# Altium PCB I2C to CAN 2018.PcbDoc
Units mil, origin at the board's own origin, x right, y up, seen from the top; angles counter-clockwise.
Board outline 2285 x 2910 mil, 2 copper layers (Top Layer, Bottom Layer), stack 62 mil thick; 55 components, 23 nets, 109 pads, 24 vias.
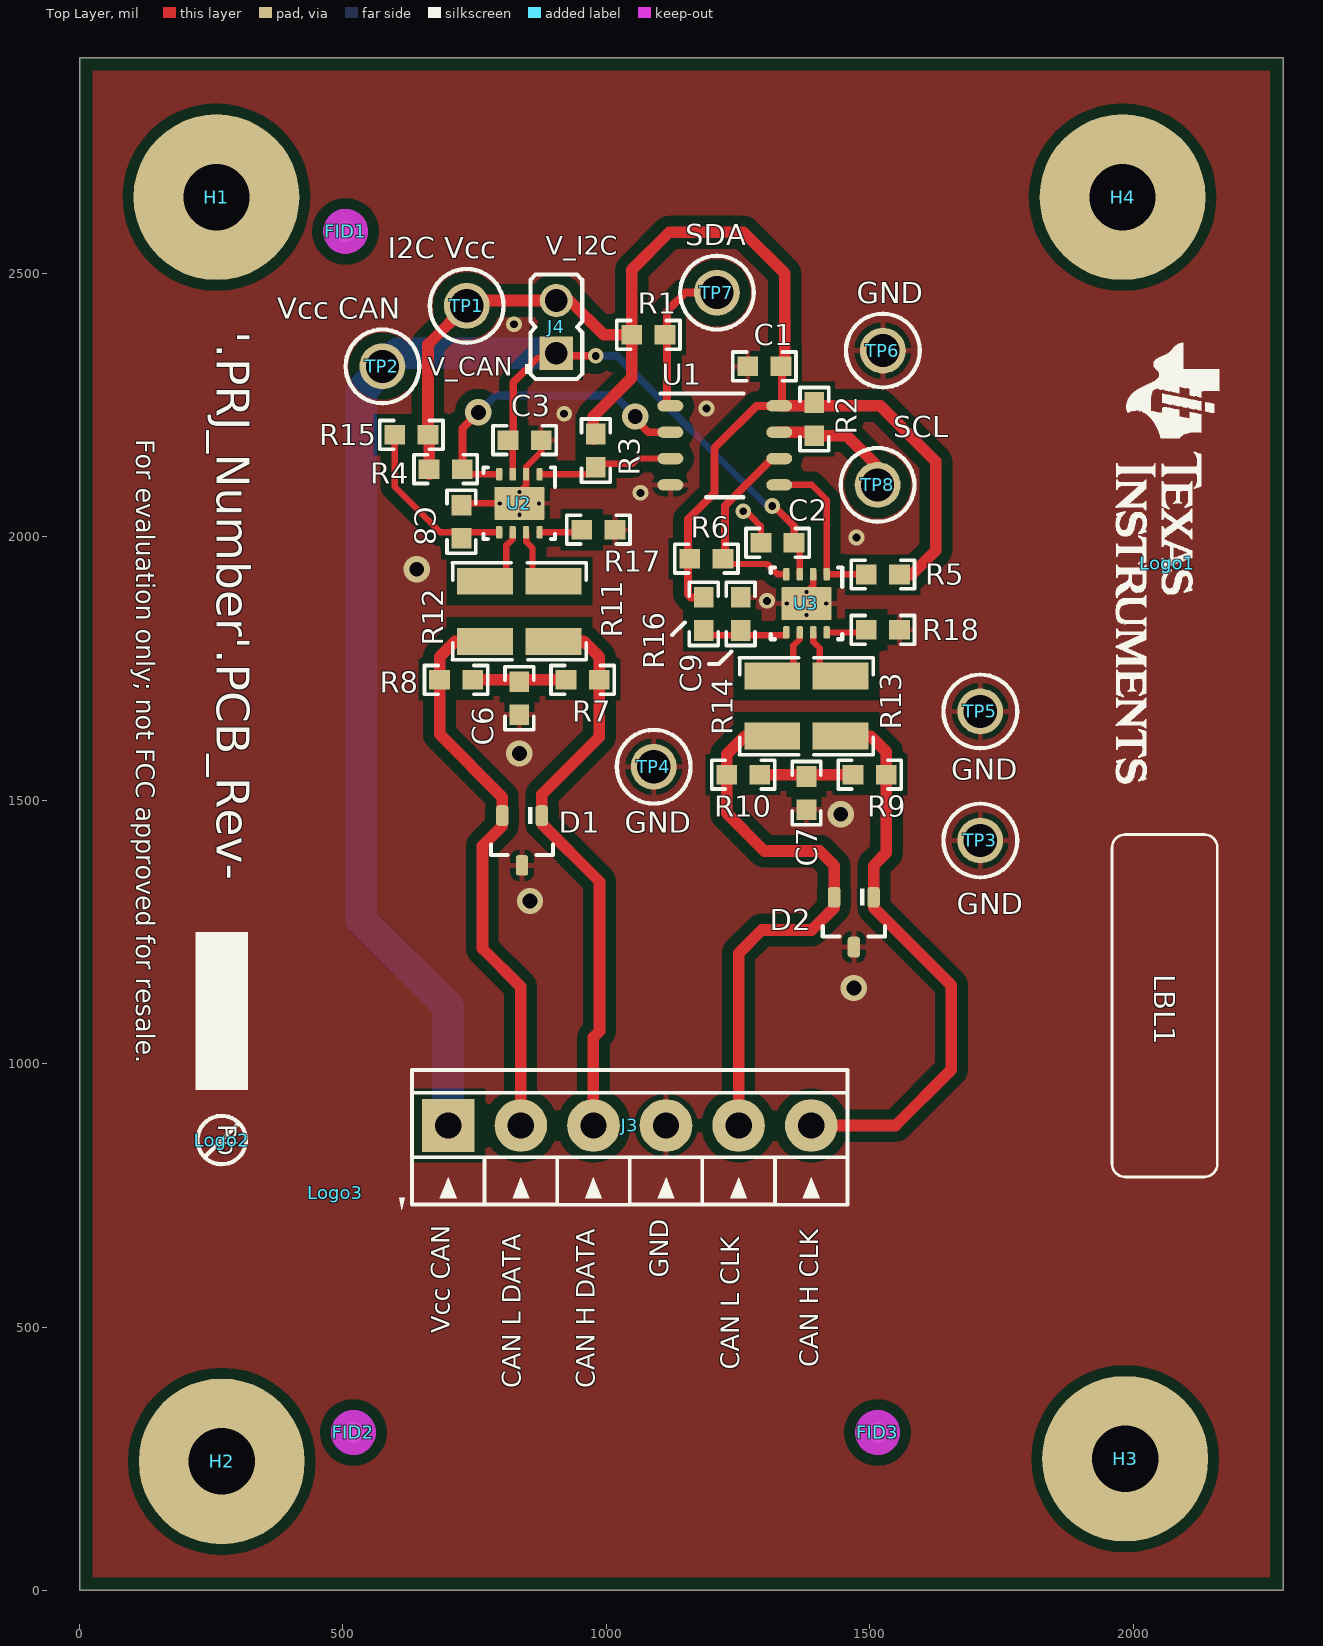
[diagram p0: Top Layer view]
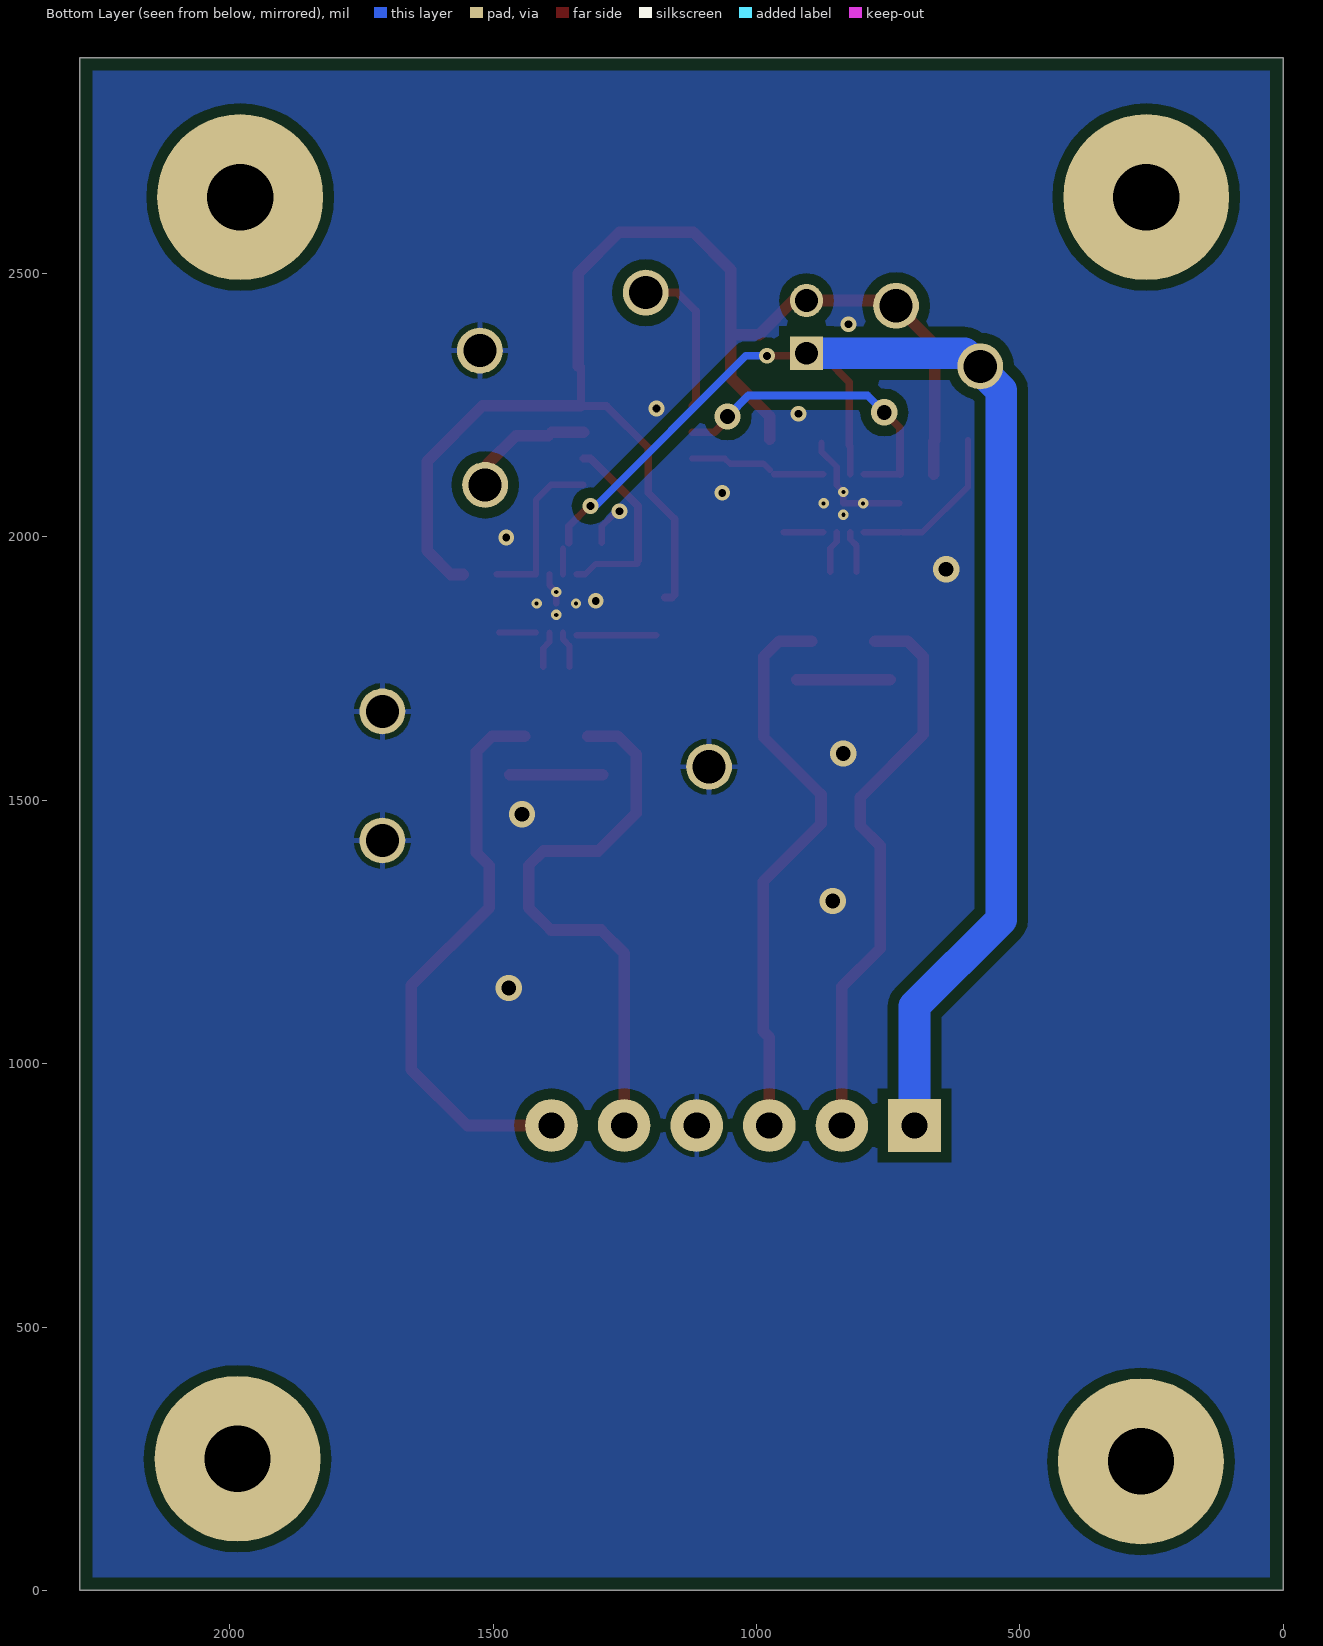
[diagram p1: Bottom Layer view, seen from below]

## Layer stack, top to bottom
Top Solder: solder mask 0.4, Solder Resist, Dk 3.5
Top Layer: signal copper 1.4
Dielectric1: core 59.2, FR-4, Dk 4.8
Bottom Layer: signal copper 1.4
Bottom Solder: solder mask 0.4, Solder Resist, Dk 3.5

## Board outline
0,0 2285,0 2285,2910 0,2910

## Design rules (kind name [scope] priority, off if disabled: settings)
AcuteAngle [All] p1: minimum=4.50000000000000E+0001 checktracksonly=FALSE
AssemblyTestPointUsage [All] p1: valid=2
BoardOutlineClearance BoardOutlineClearance_MountingHoles [OnCopper and InComponentClass('Mounting Holes')] p1: gap=40 ignorepadtopadclearanceinfootprint=FALSE
BoardOutlineClearance BoardOutlineClearance_Poly [OnCopper and IsPoly] p2: gap=25 ignorepadtopadclearanceinfootprint=FALSE
BoardOutlineClearance [OnCopper and Not InComponentClass('Logo') and not InComponentClass('FiducialMark') and not InRegion(1000,500,4000,800) and not InPoly] p3: gap=75 ignorepadtopadclearanceinfootprint=FALSE
Clearance Clearance_Keepouts [((IsTrack Or IsArc) And Not InPoly) And IsFree and IsKeepOut vs ((IsTrack Or IsArc) And Not InPoly) And IsFree and IsKeepOut] p1: gap=0 ignorepadtopadclearanceinfootprint=FALSE
Clearance Clearance_Poly [InPolygon] p2: gap=20 ignorepadtopadclearanceinfootprint=FALSE
Clearance Clearance_FiducialMark [IsKeepOut and InComponentClass('FiducialMark') vs IsPad and InComponentClass('FiducialMark')] p3: gap=0 ignorepadtopadclearanceinfootprint=FALSE
Clearance [All] p4: gap=7.87 ignorepadtopadclearanceinfootprint=FALSE except(0: Arc-Hole Track-Hole SMDPad-Hole THPad-Hole Via-Hole Fill-Hole Poly-Hole Region-Hole Text-Hole)
ComponentClearance ComponentClearance_MountingHoles_FiducialMarks [InComponentClass('Mounting Holes') vs InComponentClass('FiducialMark')] p1: gap=50 collisioncheckmode=3 verticalgap=10 showdistances=FALSE
ComponentClearance ComponentClearance_Shunt [InComponentClass('Header') vs InComponentClass('Shunt')] p2: gap=0 collisioncheckmode=3 verticalgap=0 showdistances=FALSE
ComponentClearance ComponentClearance_Logo [InComponentClass('Logo')] p3: gap=50 collisioncheckmode=3 verticalgap=10 showdistances=FALSE
ComponentClearance ComponentClearance_ScrewToNut [(HasFootprint('NY PMS 440 0025 PH')) vs (HasFootprint('Keystone_1902C'))] p4: gap=5 collisioncheckmode=3 verticalgap=10 showdistances=FALSE
ComponentClearance ComponentClearance_MountingHoles [InComponentClass('Mounting Holes')] p5: gap=250 collisioncheckmode=3 verticalgap=100000 showdistances=FALSE
ComponentClearance ComponentClearance_SmallPassives [HasFootprint('0201*') or HasFootprint('0402*') or HasFootprint('0508') or HasFootprint('0603*') or HasFootprint('0612') or HasFootprint('0805*') or HasFootprint('0815*') or HasFootprint('0830*') or HasFootprint('1206*') or HasFootprint('1210*') or HasFootprint('1808*') or HasFootprint('1812*') or HasFootprint('1825*') or HasFootprint('2010*') or HasFootprint('2220*') or HasFootprint('2225*') or HasFootprint('2512*') or HasFootprint('2728*') or HasFootprint('3518*') vs HasFootprint('0201*') or HasFootprint('0402*') or HasFootprint('0508') or HasFootprint('0603*') or HasFootprint('0612') or HasFootprint('0805*') or HasFootprint('0815*') or HasFootprint('0830*') or HasFootprint('1206*') or HasFootprint('1210*') or HasFootprint('1808*') or HasFootprint('1812*') or HasFootprint('1825*') or HasFootprint('2010*') or HasFootprint('2220*') or HasFootprint('2225*') or HasFootprint('2512*') or HasFootprint('2728*') or HasFootprint('3518*')] p6: gap=14.96 collisioncheckmode=3 verticalgap=10 showdistances=FALSE
ComponentClearance ComponentClearance_THtoSMT [IsThruComponent vs IsSMTComponent] p7: gap=40 collisioncheckmode=3 verticalgap=30 showdistances=FALSE
ComponentClearance ComponentClearance_THtoTH [IsThruComponent vs IsThruComponent] p8: gap=30 collisioncheckmode=3 verticalgap=30 showdistances=FALSE
ComponentClearance [All] p9: gap=30 collisioncheckmode=3 verticalgap=10 showdistances=FALSE
DiffPairsRouting [All] p1: maxlimit=100 minlimit=10 mostfreqgap=10 toplayer_minwidth=15 toplayer_maxwidth=15 toplayer_prefwidth=15 bottomlayer_minwidth=15 bottomlayer_maxwidth=15 bottomlayer_prefwidth=15 maxuncoupledlength=1000
FabricationTestPointUsage TestPointUsage [All] p1: valid=2 allowmultiple=FALSE
FabricationTestpoint Testpoint [All] p1: side=3 testpointundercomponent=TRUE minsize=40 maxsize=100 preferedsize=60 minholesize=0 maxholesize=40 preferedholesize=32 testpointgrid=1 allowsidetop=TRUE allowsidebottom=TRUE usegrid=TRUE gridtolerance=0.01
FanoutControl Fanout_LCC [IsLCC] p1: bgadir=Out bgaviamode=Centered fanoutstyle=Auto fanoutdirection=Alternating viagrid=1 // Fanout_LCC (Default Rule)
FanoutControl Fanout_BGA [IsBGA] p2: bgadir=Out bgaviamode=Centered fanoutstyle=Auto fanoutdirection=Alternating viagrid=1 // Fanout_BGA (Default Rule)
FanoutControl Fanout_Default [All] p4: bgadir=Out bgaviamode=Centered fanoutstyle=Auto fanoutdirection=Alternating viagrid=1 // Fanout_Default (Default Rule)
FanoutControl Fanout_Small [(CompPinCount < 5)] p5: bgadir=Out bgaviamode=Centered fanoutstyle=Auto fanoutdirection=OutThenIn viagrid=1 // Fanout_Small (Default Rule)
HoleSize [All] p1: absolutevalues=TRUE maxlimit=251 minlimit=7.87 maxpercent=80.000 minpercent=20.000
MatchedLengths "Can Length 2" [InNetClass('Can Length 2')] p1: tolerance=5 checknetsindiffpair=FALSE checkdiffpairvsdiffpair=TRUE checkxsignals=TRUE checkothers=TRUE
MinimumAnnularRing MinimumAnnularRing_ThermalPadVias [IsVia and InAnyComponent] p1: minimumring=5.91
MinimumAnnularRing [All] p2: minimumring=7.49
MinimumSolderMaskSliver MinimumSolderMaskSliver_Logo [InComponentClass('Logo') vs InComponentClass('Logo')] p1: minsoldermaskwidth=0.7
MinimumSolderMaskSliver [All] p2: minsoldermaskwidth=3.94
PlaneConnect [All] p1: planeconnectstyle=Relief reliefexpansion=10 reliefentries=4 reliefconductorwidth=10 reliefairgap=10
PolygonConnect "GND Vias Relief" [IsVia AND InNet('GND')] p1: thpad.connectstyle=Relief thpad.reliefconductorwidth=10 thpad.reliefentries=4 thpad.polygonreliefangle="90 Angle" thpad.airgapwidth=10 smdpad.connectstyle=Relief smdpad.reliefconductorwidth=10 smdpad.reliefentries=4 smdpad.polygonreliefangle="90 Angle" smdpad.airgapwidth=10 via.connectstyle=Direct via.reliefconductorwidth=10 via.reliefentries=4 via.polygonreliefangle="90 Angle" via.airgapwidth=10
PolygonConnect [All] p2: connectstyle=Relief reliefconductorwidth=10 reliefentries=4 polygonreliefangle="90 Angle" airgapwidth=10
RoutingVias ThermalPadVias [IsVia and InAnyComponent] p1: holewidth=7.87 width=19.68 viastyle="Through Hole" minholewidth=7.87 minwidth=19.68 maxholewidth=12.99 maxwidth=23.62
RoutingVias [All] p2: holewidth=16 width=34 viastyle="Through Hole" minholewidth=7.87 minwidth=26 maxholewidth=40 maxwidth=65
SilkToBoardRegionClearance [Not ((IsComment or IsDesignator) And (Hide <> 'False')) and not InRegion(1000,500,4000,800)] p1:
SilkToSilkClearance SilkToSilkClearance_Pb-FreeLogo [(HasFootprint('Pb-Free_Overlay_Medium') OR HasFootprint('Pb-Free_Overlay_Small')) vs (HasFootprint('Pb-Free_Overlay_Medium') OR HasFootprint('Pb-Free_Overlay_Small'))] p1: silktosilkclearance=0
SilkToSilkClearance [All] p2: silktosilkclearance=4
SilkToSolderMaskClearance SilkToComponentPadClearance [(IsPad or IsFill or IsRegion) and InAnycomponent] p1: minsilkscreentomaskgap=5 clearancetoexposedcopper=TRUE
SilkToSolderMaskClearance "Silk to Solder Mask Opening" [All] p2: minsilkscreentomaskgap=4 clearancetoexposedcopper=FALSE
SolderMaskExpansion [All] p1: expansion=1.97
Width [All] p1: maxlimit=100 minlimit=6 preferedwidth=10 checkconnectedcopper=TRUE
15 further rules are at their usual default settings.

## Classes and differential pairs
component class "Mounting Holes": H1 H2 H3 H4
net class "Can Length 1": NetR11_2 NetR12_2 NetR13_2 NetR14_2
net class "Can Length 2": "CAN H Clock" "CAN H Data" "CAN L Clock" "CAN L Data"
component class Header: J4
component class "I2C to CAN 2018": C1 C2 C3 C6 C7 C8 C9 D1 D2 J3 J4 R1 R2 R3 R4 R5 R6 R7 R8 R9 R10 R11 R12 R13 R14 R15 R16 R17 R18 TP1 TP2 TP3 TP4 TP5 TP6 TP7 TP8 U1 U2 U3
component class Label: LBL1
component class AssemblyNote: ZZ1 ZZ2 ZZ3 ZZ4
component class FiducialMark: FID1 FID2 FID3
component class EVM_Hardware: FID1 FID2 FID3 H1 H2 H3 H4 LBL1 Logo1 Logo2 Logo3 ZZ1 ZZ2 ZZ3 ZZ4
component class Logo: Logo1

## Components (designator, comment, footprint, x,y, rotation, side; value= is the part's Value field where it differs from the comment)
C1 "885012206020" 0603 1300,2323.7 r180 top value=0.1uF
C2 "885012206020" 0603 1325,1988.7 r180 top value=0.1uF
C3 "885012206020" 0603 845,2183.7 r0 top value=0.1uF
C6 "C1608X5R1H104K080AA" 0603 835,1693.7 r90 top value=0.1uF
C7 "C1608X5R1H104K080AA" 0603 1380,1513.7 r90 top value=0.1uF
C8 "885012206020" 0603 725,2028.7 r90 top value=0.1uF
C9 "885012206020" 0603 1255,1853.7 r90 top value=0.1uF
D1 "NUP2105LT1G" SOT-23 840,1423.7 r270 top value=24V
D2 "NUP2105LT1G" SOT-23 1470,1268.7 r270 top value=24V
FID1 "Fiducial" Fiducial10-20 505,2580 r0 top
FID2 "Fiducial" Fiducial10-20 520,300 r0 top
FID3 "Fiducial" Fiducial10-20 1515,300 r0 top
H1 "NY PMS 440 0025 PH" "NY PMS 440 0025 PH" 260,2645 r90 top
H2 "NY PMS 440 0025 PH" "NY PMS 440 0025 PH" 270,245 r90 top
H3 "NY PMS 440 0025 PH" "NY PMS 440 0025 PH" 1985,250 r90 top
H4 "NY PMS 440 0025 PH" "NY PMS 440 0025 PH" 1980,2645 r90 top
J3 "ED555/6DS" TERM_BLK_ED555-6DS 700,882.7 r0 top
J4 "Vcc Connect" 3M_961102-6404-AR 905,2398.7 r90 top
LBL1 "Size: 0.65\" x 0.20 \"" Label_650x200 2060,1110 r270 top
Logo1 "Texas Instruments" TI_Stacked_Overlay_Small 2065,1950 r270 top
Logo2 "Pb-Free Symbol" Pb-Free_Overlay_Small 270,855 r270 top
Logo3 "FCC disclaimer" FCC_disclaimer 485,755 r270 top
R1 "RT0603BRD074K7L" 0603 1080,2383.7 r180 top value=4.70k
R2 "RT0603BRD074K7L" 0603 1395,2223.7 r90 top value=4.70k
R3 "RT0603BRD074K7L" 0603 980,2163.7 r90 top value=4.70k
R4 "RT0603BRD074K7L" 0603 695,2128.7 r180 top value=4.70k
R5 "RT0603BRD074K7L" 0603 1525,1928.7 r0 top value=4.70k
R6 "RT0603BRD074K7L" 0603 1190,1958.7 r180 top value=4.70k
R7 "CRCW060362R0JNEA" 0603 955,1728.7 r0 top value=62
R8 "CRCW060362R0JNEA" 0603 715,1728.7 r0 top value=62
R9 "CRCW060362R0JNEA" 0603 1500,1548.7 r0 top value=62
R10 "CRCW060362R0JNEA" 0603 1260,1548.7 r0 top value=62
R11 "CRCW12100000Z0EA" 1210 900,1858.7 r90 top value=0
R12 "CRCW12100000Z0EA" 1210 770,1858.7 r90 top value=0
R13 "CRCW12100000Z0EA" 1210 1445,1678.7 r90 top value=0
R14 "CRCW12100000Z0EA" 1210 1315,1678.7 r90 top value=0
R15 "RT0603BRD074K7L" 0603 630,2193.7 r0 top value=4.70k
R16 "RT0603BRD074K7L" 0603 1185,1853.7 r90 top value=4.70k
R17 "RT0603BRD074K7L" 0603 985,2013.7 r180 top value=4.70k
R18 "RT0603BRD074K7L" 0603 1525,1823.7 r180 top value=4.70k
TP1 "I2C Vcc" Keystone5010 735,2438.7 r0 top
TP2 "Vcc CAN" Keystone5010 575,2323.7 r0 top
TP3 "GND" Keystone5011 1710,1423.7 r0 top
TP4 "GND" Keystone5011 1090,1563.7 r0 top
TP5 "GND" Keystone5011 1710,1668.7 r0 top
TP6 "GND" Keystone5011 1525,2353.7 r0 top
TP7 "SDA" Keystone5010 1210,2463.7 r0 top
TP8 "SCL" Keystone5010 1515,2098.7 r0 top
U1 "P82B96D" D0008A_L 1225,2173.7 r0 top
U2 "TCAN1042HGVDRBQ1" DRB0008F 834.99,2063.71 r270 top
U3 "TCAN1042HGVDRBQ1" DRB0008F 1380,1873.7 r270 top
ZZ1 "This Assembly Note is for PCB labels only" AssemblyNoteLabel 185,3938 r0 top
ZZ2 "This Assembly Note will show in the PcbDoc and associated outputs" AssemblyNote 185,3829.11 r0 top
ZZ3 "This Assembly Note will show in the PcbDoc and associated outputs" AssemblyNote 185,3740.56 r0 top
ZZ4 "This Assembly Note will show in the PcbDoc and associated outputs" AssemblyNote 185,3652 r0 top

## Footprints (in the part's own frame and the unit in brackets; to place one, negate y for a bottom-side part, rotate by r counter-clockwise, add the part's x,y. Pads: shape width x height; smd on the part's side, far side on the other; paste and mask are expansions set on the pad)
3M_961102-6404-AR [mm] "Header, 2.54mm, 2x1, TH"
  rect 1.6x1.6 hole 1.1: 1(-1.27,0)
  round 1.6 hole 1.1: 2(1.27,0)
  silkscreen extent -2.52,-1.25 2.52,1.5, body extent -2.52,-1.25 2.52,1.25, height 8.5
0603 [mm] "0603 from SM-752 data"
  rect 1x0.95 smd: 1(-0.8,0) 2(0.8,0)
  silkscreen extent -1.52,-0.69 1.52,0.69, body extent -0.87,-0.47 0.87,0.47, height 1
1210 [mm] "1210 from SM-752 data"
  rect 1.3x2.7 smd: 1(-1.45,0) 2(1.45,0)
  silkscreen extent -2.34,-1.57 2.34,1.27, body extent -1.7,-1.35 1.7,1.35, height 1.35
AssemblyNote [mil] "Assembly Note"
AssemblyNoteLabel [mil] "Assembly Note for PCB Labels"
D0008A_L [mm] "SOIC, 8-Leads, Body 4.9x3.9mm, Pitch 1.27mm, IPC High Density"
  oval 1.25x0.55 smd: 1(-2.625,1.905) 2(-2.625,0.635) 3(-2.625,-0.635) 4(-2.625,-1.905) 5(2.625,-1.905) 6(2.625,-0.635) 7(2.625,0.635) 8(2.625,1.905)
  silkscreen extent -3.1,-2.5 0.9,2.5, body extent -3,-2.45 3,2.45, height 1.63
DRB0008F [mm] "SON, 8-Leads, Body 3x3mm, Pitch 0.65mm, Thermal Pad 2.4x1.6mm, TI Recommended"
  rrect33% 0.6x0.3 smd: 1(-1.4,0.975) 2(-1.4,0.325) 3(-1.4,-0.325) 4(-1.4,-0.975) 5(1.4,-0.975) 6(1.4,-0.325) 7(1.4,0.325) 8(1.4,0.975)
  rrect9% 1.47x1.07 on Top Paste: 9(0,0.635) 9(0,-0.635)
  rrect6% 1.6x2.4 smd paste-1.2: 9(0,0)
  silkscreen extent -1.73,-1.73 1.73,1.73, body extent -1.5,-1.5 1.5,1.5, height 0.77
FCC_disclaimer [mil]
Fiducial10-20 [mm]
  round 1 smd mask+0.5: 1(0,0)
  Top Layer keep-out circle w1.178: c0,0 r0.5
Keystone5010 [mil] "Keystone Multipurpose loops"
  round 87 hole 63: 1(0,0)
  silkscreen extent -70,-70 70,70, body extent -63,-63 63,62, height 319
Keystone5011 [mil] "Keystone Multipurpose loops"
  round 87 hole 63: 1(0,0)
  silkscreen extent -70,-70 70,70, body extent -63,-63 63,62, height 319
Label_650x200 [mil] "Thermal Transfer Label"
  silkscreen extent -325,-100 325,100, body extent -325,-100 325,100, height 1
"NY PMS 440 0025 PH" [mm] "4-40 nylon screw and mounting hole"
  round 8 hole 3.2: 1(0,0)
  body extent -3.3,-3.3 3.3,3.3, height 2.69
Pb-Free_Overlay_Small [mil]
  silkscreen extent -46,-46 46,46
SOT-23 [mm] "SOT23, 3-Leads, Body 2.9x1.3mm, Pitch 0.95mm, Lead Span 2.5mm, IPC Medium Density"
  rrect50% 1x0.6 smd: 1(-1.2,0.95) 2(-1.2,-0.95) 3(1.2,0)
  silkscreen extent -1.63,-1.5 0.7,1.5, body extent -1.16,-1.45 1.21,1.45, height 1
TERM_BLK_ED555-6DS [mm]
  rect 2.54x2.54 hole 1.27: 1(0,0)
  round 2.54 hole 1.27: 2(3.5,0) 3(7,0) 4(10.5,0) 5(14,0) 6(17.5,0)
  silkscreen extent -2.36,-4.09 19.25,2.67, body extent -1.75,-3.8 19.25,2.7, height 8.2
TI_Stacked_Overlay_Small [mil]
  silkscreen extent -418,-98 418,98

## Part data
C1 C2 C3 C8 C9: library part CMP-0064931-2, "CAP, CERM, 0.1 uF, 10 V,+/- 10%, X7R, 0603", Cap_Case=0603, Manufacturer="Wurth Elektronik", Supplier Part Number 1=732-7939-1-ND, TempCo=X7R, Tolerance_%=10%, Value1=Unknown, Value2=10V, ValueDisplayed=0.1uF
C6 C7: library part CMP-0007010-2, "CAP, CERM, 0.1 uF, 50 V, +/- 10%, X5R, 0603", Cap_Case=0603, Manufacturer=TDK, Supplier Part Number 1=445-7456-1-ND, TempCo=X5R, Tolerance_%=10%, Value1="0.0296 ohm", Value2=50V, ValueDisplayed=0.1uF
D1 D2: library part CMP-0005919-2, "Diode, TVS, Bi, 24 V, SOT-23", Manufacturer="ON Semiconductor", Power_W=350mW, Supplier Part Number 1=NUP2105LT1GOSCT-ND, Value1=0.35W
FID1 FID2 FID3: "Fiducial mark.  There is nothing to buy or mount.", Manufacturer=N/A
H1 H2 H3 H4: "Machine Screw, Round, #4-40 x 1/4, Nylon, Philips panhead", DigiKeyPartNumber=H542-ND, Manufacturer="B&F Fastener Supply"
J3: "Terminal Block, 3.5mm Pitch, 6x1, TH", Color=Grey, Current_A=6, Manufacturer="On-Shore Technology", Supplier Part Number 1=ED1518-ND, Voltage_V=150
J4: library part 961102-6404-AR, "Header, 2.54mm, 2x1, TH", Color=Black, Current_A=2, Manufacturer=3M, Supplier Part Number 1=3M9447-ND, Voltage_V=1000
LBL1: library part THT-14-423-10, "Thermal Transfer Printable Labels, 0.650\" W x 0.200\" H - 10,000 per roll", Manufacturer=Brady, Supplier Part Number 1=97C5133
Logo1: library part TI_Logo, "Texas Instrument Corporate Signature"
Logo2: library part Pb-Free
Logo3: library part FCC_disclaimer, "FCC_disclaimer"
R1 R2 R3 R4 R5 R6: library part CMP-0024300-1, "RES, 4.70 k, 0.1%, 0.1 W, 0603", Manufacturer="Yageo America", Power_W=100mW, TempCo="25 ppm/C", Tolerance_%=0.1%, Value2=0.1W, Value_Code=4k70, ValueDisplayed=4.70k
R7 R8 R9 R10: library part CMP-0025839-2, "RES, 62, 5%, 0.1 W, 0603", Manufacturer=Vishay-Dale, Power_W=100mW, Supplier Part Number 1=541-62GCT-ND, TempCo="200 ppm/C", Tolerance_%=5%, Value2=0.1W, Value_Code=62R0, ValueDisplayed=62
R11 R12 R13 R14: library part CMP-0015016-2, "RES, 0, 1%, 0.5 W, AEC-Q200 Grade 0, 1210", Manufacturer=Vishay-Dale, Power_W=500mW, Supplier Part Number 1=541-0.0VCT-ND, TempCo=ppm/C, Tolerance_%=1%, Value2=0.5W, Value_Code=0
R15 R16 R17 R18: library part CMP-0024300-1, "RES, 4.70 k, 0.1%, 0.1 W, 0603", Manufacturer="Yageo America", Power_W=100mW, TempCo="25 ppm/C", Tolerance_%=0.1%, Value2=0.1W, Value_Code=4k70, ValueDisplayed=0
TP1 TP2 TP7 TP8: library part 5010, "Test Point, Multipurpose, Red, TH", Color=Red, Manufacturer=Keystone, Supplier Part Number 1=36-5010-ND
TP3 TP4 TP5 TP6: library part 5011, "Test Point, Multipurpose, Black, TH", Color=Black, Manufacturer=Keystone, Supplier Part Number 1=36-5011-ND
U1: library part CMP-0043184-1, "Dual Bidirectional Bus Buffer, 2 Channel Width, 2.0 to 15.0 V, -40 to 85 degC, 8-pin SOIC (D), Green (RoHS & no Sb/Br)", 5V Tolerant I/O=Yes, Manufacturer="Texas Instruments", Master Side I2C Bus Capacitance Supported(pF)=400
U2 U3: library part CMP-0065183-2, "Automotive Fault Protected CAN Transceiver With Flexible Data-Rate, DRB0008F (VSON-8)", Alternate Manufacturer="Texas Instruments"
ZZ1: library part AssemblyNoteLabel
ZZ2 ZZ3 ZZ4: library part AssemblyNote

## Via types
v1: diameter 30, hole 15, Top Layer to Bottom Layer, 9 vias
v2: diameter 19.68, hole 7.87, Top Layer to Bottom Layer, 8 vias
v3: diameter 50, hole 28, Top Layer to Bottom Layer, 7 vias

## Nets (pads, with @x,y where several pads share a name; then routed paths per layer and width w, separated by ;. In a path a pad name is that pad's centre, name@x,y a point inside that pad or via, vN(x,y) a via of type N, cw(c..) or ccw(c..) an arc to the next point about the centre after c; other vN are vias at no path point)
"CAN H Clock": D2.1 J3.6 R9.2 R13.1 | length 1088.2
  Top Layer w22: J3.6 1549,882.7 1655,988.7 1655,1148.7 1507.4,1296.3 D2.1 1507.4,1376.1 1531.5,1400.2 R9.2 1531.5,1592.2 1502.09,1621.61 R13.1 R13.1@1440,1621.61
"CAN H Data": D1.1 J3.3 R7.2 R11.1 | length 1088.5
  Top Layer w22: R11.1@895,1801.61 R11.1 957.09,1801.61 986.5,1772.2 R7.2 986.5,1620.2 877.4,1511.1 D1.1 877.4,1455.3 987,1345.7 987,1061.7 975.59,1050.29 J3.3
"CAN L Clock": D2.2 J3.5 R10.1 R14.1 | length 1087.1
  Top Layer w22: J3.5 1251.18,1209.88 1295,1253.7 1390,1253.7 1432.6,1296.3 D2.2 1432.6,1376.1 1405,1403.7 1300,1403.7 1228.5,1475.2 R10.1 1228.5,1587.2 1262.91,1621.61 R14.1 R14.1@1320,1621.61
"CAN L Data": D1.2 J3.2 R8.1 R12.1 | length 1088.2
  Top Layer w22: R12.1@775,1801.61 R12.1 712.91,1801.61 683.5,1772.2 R8.1 683.5,1625.2 802.6,1506.1 D1.2 802.6,1451.3 765,1413.7 765,1218.7 837.8,1145.91 J3.2
GND: C1.2 C2.2 C3.2 C6.1 C7.1 C8.2 C9.2 D1.3 D2.3 J3.4 R17.1 R18.1 TP3.1 TP4.1 TP5.1 TP6.1 U1.4 U2.2 U2.9@834.99,2063.71 U3.2 U3.9@1380,1873.7 | length 375.9
  Top Layer w12: C8.2@728.51,2063.71 834.99,2063.71 v2(834.99,2085.36) 847.79,2098.15 U2.2 847.79,2132.94 876.5,2161.65 C3.2@876.5,2178.7 ; v1(1260,2048.7) 1265,2048.7 1275,2038.7 1293.5,2020.2 C2.2 ; U3.9@1380,1873.7 v2(1380,1895.35) 1392.8,1908.15 U3.2
  other v1: 1305,1878.7 1475,1998.7 1065,2083.7 920,2233.7 1190,2243.7 825,2403.7
  other v2: 1380,1852.05 1342.6,1873.7 1417.4,1873.7 834.99,2042.05 797.59,2063.71 872.39,2063.71
  other v3: 1470,1143.7 855,1308.7 1445,1473.7 835,1588.7 640,1938.7
"I2C Vcc": C1.1 J4.2 R1.2 R2.2 R3.2 R4.2 R5.2 R6.2 R15.2 R16.2 TP1.1 U1.8 | length 2722.4
  Top Layer w15: R16.2@1173.5,1885.2 1160.24,1885.2 1155,1890.43 1155,2033.7 1205.31,2084.02 1205.31,2169.02 1285,2248.7 1333.35,2248.7 C1.1@1333.35,2323.54
  Top Layer w22: R15.2@661.49,2183.7 661.49,2365.19 TP1.1 745,2448.7 930,2448.7 995,2383.7 R1.2 ; R4.2@663.5,2118.7 R15.2@663.5,2181.7 ; R3.2@975,2185.2 975,2228.7 1048.5,2302.2 R1.2 ; U1.8@1333.35,2248.7 1520,2248.7 1625,2143.7 1625,1973.7 1580,1928.7 R5.2 ; C1.1@1338.5,2323.7 1338.5,2500.2 1260,2578.7 1120,2578.7 1048.5,2507.2 R1.2
NetC6_2: C6.2 R7.1 R8.2 | length 177
  Top Layer w22: R8.2 R7.1
NetC7_2: C7.2 R9.1 R10.2 | length 177
  Top Layer w22: R10.2 R9.1
NetC8_1: C8.1 R15.1 U2.5 | length 315.5
  Top Layer w12: R15.1@598.5,2183.7 598.5,2095.2 685,2008.7 C8.1@721.5,2008.7 ; C8.1@728.38,2008.59 U2.5
NetC9_1: C9.1 R16.1 U3.5 | length 151.6
  Top Layer w12: R16.1@1190,1813.58 U3.5@1341.61,1813.58
NetR1_1: R1.1 TP7.1 U1.1 | length 292.3
  Top Layer w15: U1.1 1115,2255.35 1115,2428.7 1150,2463.7 TP7.1
NetR2_1: R2.1 TP8.1 U1.7 | length 237.3
  Top Layer w22: U1.7 R2.1@1388.5,2198.7 ; R2.1 1456.5,2192.2 1510,2138.7 TP8.1@1510,2098.7
NetR3_1: R3.1 U1.3 U2.1 | length 248.8
  Top Layer w12: U2.1 R3.1@966.61,2118.82 ; R3.1@975,2127.21 986.49,2138.7 1050,2138.7 1060,2148.7 U1.3
NetR4_1: R4.1 U1.2 U2.4 | length 609.4
  Top Layer w12: R4.1@726.49,2118.7 726.61,2118.82 U2.4
  Top Layer w15: R4.1@727.18,2119.39 727.18,2206.32 v3(757.18,2236.32) ; v3(1055,2228.6) 1055,2223.5 1079.8,2198.7 U1.2
  Bottom Layer w15: v3(757.18,2236.32) 789.56,2268.7 1014.9,2268.7 v3(1055,2228.6)
NetR5_1: R5.1 U1.5 U3.1 | length 318.3
  Top Layer w12: U1.5 1390,2098.7 1418.39,2070.31 U3.1 R5.1@1493.39,1928.82
NetR6_1: R6.1 U1.6 U3.4 | length 367.5
  Top Layer w12: R6.1@1226.5,1948.7 1305,1948.7 1324.88,1928.82 U3.4
  Top Layer w15: R6.1@1225,1955.2 1225,2058.7 1315,2148.7 U1.6
NetR11_2: R11.2 U2.7 | length 79.9
  Top Layer w12: U2.7 847.79,1990.91 860,1978.7 R11.2@860,1933.7
NetR12_2: R12.2 U2.6 | length 79.9
  Top Layer w12: R12.2@810,1933.7 810,1983.7 822.2,1995.9 U2.6
NetR13_2: R13.2 U3.7 | length 69.9
  Top Layer w12: U3.7 1392.8,1800.91 1405,1788.7 R13.2@1405,1753.7
NetR14_2: R14.2 U3.6 | length 69.9
  Top Layer w12: R14.2@1355,1753.7 1355,1793.7 1367.2,1805.91 U3.6
STB1: R17.2 U2.8 | length 75
  Top Layer w12: U2.8@873.49,2008.7 R17.2@948.5,2008.7
STB2: R18.2 U3.8 | length 70
  Top Layer w12: U3.8 R18.2@1488.39,1818.58
"Vcc CAN": C2.1 C3.1 J3.1 J4.1 TP2.1 U2.3 U3.3 | length 2784.7
  Top Layer w12: U2.3 C3.1@822.2,2172.4 ; U3.3 C2.1@1367.2,1977.99
  Top Layer w14: C3.1@823.5,2173.7 823.5,2293.7 868.5,2338.7 905,2347.32 908.61,2343.7 v1(980,2343.7) ; v1(1315,2058.7) 1317.92,2058.7 1356.5,2020.13 C2.1
  Bottom Layer w14: v1(980,2343.7) 1020,2343.7 1305,2058.7 v1(1315,2058.7)
  Bottom Layer w60: J3.1@700,893.7 700,1108.7 535,1273.7 535,2278.7 605,2348.7 J4.1@895,2348.7
pads on no net: FID1.1 FID2.1 FID3.1 H1.1 H2.1 H3.1 H4.1 U2.9@809.99,2063.71 U2.9@859.99,2063.71 U3.9@1355,1873.7 U3.9@1405,1873.7

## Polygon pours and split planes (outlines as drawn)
GND on Top Layer "TOP_LAYER_GND_P000" (solid, remove dead copper, pour order 0): 2285,2910 2285,5 10,5 10,2355 -545,2910
GND on Bottom Layer "BOTTOM_LAYER_GND_P002" (solid, remove dead copper, pour order 2): 10,2910 2285,2910 2285,5 10,5

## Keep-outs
Keep-Out Layer:
  text ".Layer_Name" at 577,-858.49 h60

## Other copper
Top Layer:
  text ".Layer_Name" at 577,-858.49 h60
Bottom Layer:
  text ".Layer_Name" at 577,-858.49 h60

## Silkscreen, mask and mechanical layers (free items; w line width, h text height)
Top Overlay:
  region: 320,950 320,1250 220,1250 220,950
  lines w8: 1125,1813.7 1148.82,1837.52 ; 1195,1758.7 1213.5,1758.7 1237.32,1782.52
  text "V_I2C" at 885,2523.7 h60
  text "'.PRJ_Number'.PCB_Rev-" at 240,2390 h108.27 r270
  text "V_CAN" at 661.49,2293.7 h60
  text "GND" at 1130,593.7 h60 r90
  text "Vcc CAN" at 715,488.7 h60 r90
  text "CAN H CLK" at 1415,423.7 h60 r90
  text "CAN L CLK" at 1265,418.7 h60 r90
  text "CAN L DATA" at 850,383.7 h60 r90
  text "CAN H DATA" at 990,383.7 h60 r90
  text ".Layer_Name" at 577,-858.49 h60
Bottom Overlay:
  text ".Layer_Name" at 577,-858.49 h60
Top Paste:
  text ".Layer_Name" at 577,-858.49 h60
Bottom Paste:
  text ".Layer_Name" at 577,-858.49 h60
Top Solder:
  text ".Layer_Name" at 577,-858.49 h60
  text ".Layer_Name" at 577,-858.49 h60
Bottom Solder:
  text ".Layer_Name" at 577,-858.49 h60
Drill Guide:
  text ".Layer_Name" at 577,-858.49 h60
M1 Board Outline:
  lines w10: 0,0 4950,0 4950,3450 0,3450 0,0
  text ".Layer_Name" at 577,-858.49 h60
M2 Board Dimensions:
  rectangle: 125,-400 500,-275
  rectangle: 0,-275 125,-150
  lines w7: 0,-275 1000,-275 ; 125,-400 125,-150 ; 250,-400 250,-150 ; 500,-400 500,-150 ; 750,-400 750,-150 ; 0,-400 0,-150 1000,-150 1000,-400 0,-400
  text ".Layer_Name" at 577,-858.49 h60
M3 3D STEP Top:
  text ".Layer_Name" at 577,-858.49 h60
M4 3D STEP Bottom:
  text ".Layer_Name" at 577,-858.49 h60
M5 Assembly Top:
  lines w10: -292,-930.17 6308,-930.17 ; -292,-726.83 6310,-726.83 ; -292,-523.5 -292,-1133.5 3713,-1133.5 6310,-1133.5 6310,-523.5 -291.5,-523.5 -291.5,-1133.5 1284,-1133.5 ; 2173,-1133.5 2173,-523.5 ; 3440,-726.83 3440,-523.5 ; 4280,-726.83 4280,-523.5 ; 4902,-1140 4902,-937.17
  text "COMPONENTS MARKED 'DNP' SHOULD NOT BE POPULATED." at 1153.5,-318.5 h60
  text "ASSEMBLY VARIANT:" at 1153,-434 h60
  text ".VariantName" at 2189,-434 h60
  text "PCB VIEWED FROM TOP SIDE" at -228.5,-655.67 h60
  text "BOARD #:" at 2248,-655.67 h60
  text ".PRJ_Number" at 2793.5,-655.67 h60
  text "REV:" at 3638,-655.67 h60
  text ".PCB_Rev" at 3929.5,-655.67 h60
  text "SVN REV:" at 4476,-655.67 h60
  text ".VersionControl_RevNumber" at 4982,-655.67 h60
  text "TID #:" at 2248,-859 h60
  text ".TID" at 2793.5,-859 h60
  text "PLOT NAME =" at -228.5,-1064.34 h60
  text ".plot_File_Name" at 577,-1064.34 h60
  text "GENERATED    :" at 2250,-1064.34 h60
  text ".Print_Date" at 3119.5,-1064.34 h60
  text ".Print_Time" at 3848.5,-1064.34 h60
  text "TEXAS INSTRUMENTS" at 5113,-1064.34 h60
M6 Assembly Bottom:
  lines w10: -292.5,-727.33 6309.5,-727.33 ; -290.5,-930.67 6309.5,-930.67 ; 1115.5,-1140.5 1115.5,-937.67 ; 1737.5,-727.33 1737.5,-524 ; 2577.5,-727.33 2577.5,-524 ; 3844.5,-1134 3844.5,-524 ; 4733.5,-1134 6309,-1134 6309,-524 -292.5,-524 -292.5,-1134 2304.5,-1134 6309.5,-1134 6309.5,-524
  text "COMPONENTS MARKED 'DNP' SHOULD NOT BE POPULATED." at 6102,-318 h60
  text ".VariantName" at 5058,-434 h60
  text "ASSEMBLY VARIANT:" at 6097,-434 h60
  text ".VersionControl_RevNumber" at 1035.5,-656.17 h60
  text "SVN REV:" at 1541.5,-656.17 h60
  text ".PCB_Rev" at 2088,-656.17 h60
  text "REV:" at 2379.5,-656.17 h60
  text ".PRJ_Number" at 3224,-656.17 h60
  text "BOARD #:" at 3769.5,-656.17 h60
  text "PCB VIEWED FROM BOTTOM SIDE" at 6246,-656.17 h60
  text ".TID" at 3224,-859.5 h60
  text "TID #:" at 3769.5,-859.5 h60
  text "TEXAS INSTRUMENTS" at 904.5,-1064.84 h60
  text ".Print_Time" at 2169,-1064.84 h60
  text ".Print_Date" at 2898,-1064.84 h60
  text "GENERATED    :" at 3767.5,-1064.84 h60
  text ".plot_File_Name" at 5440.5,-1064.84 h60
  text "PLOT NAME =" at 6246,-1064.84 h60
M9 Title Sheet:
  drawing of 57 lines, arcs and shapes, not listed
  text "1" at 739.84,8036.5 h70
  text "2" at 3235.5,8036.5 h70
  text "3" at 5724.84,8036.5 h70
  text "4" at 8231.51,8036.5 h70
  text "5" at 10730.5,8036.5 h70
  text "6" at 13235.5,8036.5 h70
  text "A" at -416.5,6893.5 h70
  text "A" at 14383.5,6893.5 h70
  text "B" at -416.5,4513.5 h70
  text "B" at 14383.5,4513.5 h70
  text "C" at -416.5,2138.5 h70
  text "C" at 14383.5,2138.5 h70
  text "PROJECT TITLE:" at 11343.5,277.5 h45
  text ".PRJ_Title" at 11393.5,144.17 h70
  text "DESIGNED FOR:" at 11343.5,-23.5 h45
  text ".PRJ_Customer" at 11393.5,-163.5 h70
  text "D" at -416.5,-231.5 h70
  text "D" at 14383.5,-231.5 h70
  text "FILE NAME:" at 11343.5,-323.5 h45
  text ".PCB_File_Name_No_Path" at 11393.5,-443.5 h70
  text "Texas Instruments (TI) and/or its licensors do not warrant the accuracy or completeness of this specification" at 6374,-605.34 h45
  text "ENGINEER:" at 11343.5,-613.5 h45
  text "LAYOUT BY:" at 12848.5,-613.5 h45
  text "or any information contained therein. TI and/or its licensors do not warrant that this design will meet" at 6329.01,-718 h45
  text ".PRJ_Engineer" at 11393.5,-768.49 h70
  text ".PCB_Layout" at 12899,-768.49 h70
  text "the specifications, will be suitable for your application or fit for any particular purpose, or will operate in" at 6329.01,-830.67 h45
  text ".Layer_Name" at 577,-858.49 h60
  text "ALTIUM DESIGNER VERSION:" at 12848.5,-923.5 h45
  text "an implementation. TI and/or its licensors do not warrant that the design is production worthy. You should" at 6329.01,-943.33 h45
  text "completely validate and test your design implementation to confirm the system functionality for your application." at 6374,-1056 h45
  text ".print_Scale" at 11393.5,-1056.83 h70
  text ".Application_BuildNumber" at 12899,-1056.83 h70
  text "1" at 739.84,-1263.5 h70
  text "2" at 3235.5,-1263.5 h70
  text "3" at 5724.84,-1263.5 h70
  text "4" at 8231.51,-1263.5 h70
  text "5" at 10730.5,-1263.5 h70
  text "6" at 13235.5,-1263.5 h70
M10 Fab Notes:
  drawing of 189 lines, arcs and shapes, not listed
  text "DESIGN INFORMATION" at 12382.02,6356.17 h60
  text "MIN. TRACK WIDTH:" at 11737.46,6224.05 h60
  text "8" at 12833.7,6224.05 h60
  text "MIL" at 12988.46,6224.05 h60
  text "MIN. CLEARANCE:" at 11737.46,6099.92 h60
  text "0.2" at 12773.7,6099.93 h60
  text "mm" at 12988.46,6099.92 h60
  text "MIN. VIA PAD SIZE:" at 11737.46,5975.8 h60
  text "24" at 12803.71,5975.8 h60
  text "MIL" at 12988.46,5975.8 h60
  text "0.05mm (2MIL)" at 12432.46,5845.9 h60
  text "MINIMUM ANNULAR RING" at 11408.23,5837.67 h60
  text "EXTERNAL" at 13140.46,5837.67 h60
  text "PER" at 11608.23,5727.55 h60
  text "IPC-D-275 CLASS 2 LEVEL C" at 11828.23,5727.54 h60
  text "MIL, HOLES" at 13316.46,5627.07 h60
  text "+/-" at 12924,5618.48 h60
  text "+/-" at 13778,5618.48 h60
  text "REGISTRATION TOLERANCES:" at 11408.23,5617.42 h60
  text "METAL" at 12608,5617.42 h60
  text "5" at 13184.2,5617.42 h60
  text "3" at 14017.2,5617.42 h60
  text "MIL" at 14133.46,5617.42 h60
  text "HOLE SIZE TOLERANCE (UNLESS OTHERWISE SPECIFIED):" at 11408.23,5519.1 h60
  text "+/-" at 13778,5516.23 h60
  text "3" at 14017.2,5515.17 h60
  text "MIL" at 14133.46,5515.17 h60
  text "MATERIAL:" at 11333.46,5377.52 h60
  text "FR-4 High Tg" at 12319.9,5249 h60
  text "X" at 12175.46,5241.01 h60
  text "FR-408" at 11754.46,5236.49 h60
  text "OTHER" at 13242.46,5236.49 h60
  text "62 MIL (1.6mm) +/-10%" at 12074.56,5093.46 h60
  text "X" at 11954.46,5091.01 h60
  text "THICKNESS:" at 11408.23,5085.24 h60
  text "OTHER" at 13359.46,5085.24 h60
  text "TOLERANCE:" at 11408.23,4946.92 h60
  text "X" at 12256.46,4946.92 h60
  text "ANSI IPC-6012 TYPE 3 CLASS 2" at 12434.48,4946.92 h60
  text "OTHER +/-" at 12434.46,4802.73 h60
  text "BOW & TWIST:" at 11408.23,4657.54 h60
  text "X" at 12256.46,4657.54 h60
  text "ANSI IPC-6012 TYPE 3 CLASS 2" at 12434.48,4657.54 h60
  text "OTHER +/-" at 12434.46,4510.85 h60
  text "DRILLING:" at 11333.46,4380.23 h60
  text "NC_DRILL FILES" at 13094.46,4275.04 h60
  text "REFERENCE:" at 11408.23,4271.1 h60
  text "X" at 12065.46,4271.01 h60
  text "AS SHOWN" at 12243.46,4271.1 h60
  text "X" at 12966.46,4271.1 h60
  text "OTHER" at 13392.46,4128.85 h60
  text "PTH COPPER THICKNESS:" at 11407.91,4125.32 h60
  text "X" at 12547.14,4125.32 h60
  text "20-30 um" at 12675.14,4125.32 h60
  text "BOARD FINISH:" at 11333.46,3977.73 h60
  text "SILKSCREEN:" at 11488.68,3867.6 h60
  text "X" at 12446.46,3867.6 h60
  text "TOP" at 12563.46,3867.6 h60
  text "X" at 12956.46,3867.6 h60
  text "BOTTOM" at 13074.46,3867.6 h60
  text "SILKSCREEN COLOR:" at 11488.68,3712.41 h60
  text "X" at 12445.46,3712.41 h60
  text "WHITE" at 12563.46,3712.41 h60
  text "OTHER" at 13074.46,3712.41 h60
  text "X" at 12576.46,3568.96 h60
  text "GREEN" at 12694.46,3568.96 h60
  text "OTHER" at 13312.46,3568.96 h60
  text "SOLDER RESIST COLOR:" at 11488.68,3562.1 h60
  text "X" at 12576.46,3414.71 h60
  text "MATTE" at 12694.46,3414.71 h60
  text "SEMI-GLOSS" at 13312,3414.07 h60
  text "IMMERSION GOLD (ENIG)" at 12394.46,3241.94 h60
  text "ENEPIG" at 13732,3234.72 h60
  text "SURFACE FINISH:" at 11333.46,3233.72 h60
  text "X" at 12216.46,3233.72 h60
  text "IMM. TIN/SILVER OR EQUIV" at 11663,3096.4 h60
  text "OTHER" at 13094.46,3092.47 h60
  text "ARRAY/PANEL:" at 11333.46,2937.09 h60
  text "CUT AND TRIM PER M1 BOARD OUTLINE" at 12394.46,2928.87 h60
  text "N.C. ROUTE" at 12394.46,2792.9 h60
  text "X" at 13082.46,2792.9 h60
  text "V. SCORE" at 13260.46,2792.9 h60
  text "CERTIFICATION:" at 11333.46,2663.77 h60
  text "MATERIALS AND WORKMANSHIP FOR ALL PCBS" at 12058.46,2663.77 h60
  text "TO MEET OR EXCEED THE REQUIREMENTS OF:" at 12058.46,2569.71 h60
  text "X" at 11695.97,2441.08 h60
  text "ANSI IPC-A-600F CLASS ->" at 11823.96,2441.08 h60
  text "X" at 13471.97,2441.08 h60
  text "2" at 13581.96,2441.08 h60
  text "1" at 13266.96,2439.58 h60
  text "3" at 13935.96,2439.58 h60
  text "X" at 12507.97,2293.39 h60
  text "RoHS" at 12635.96,2293.39 h60
  text "OTHER" at 13280.36,2293.39 h60
  text "PER ORDER" at 13677.42,2293.39 h60
  text "ALL BOARDS MUST MEET OR EXCEED UL94-V0 REQUIREMENTS." at 11361,2139.57 h60
  text "PCB MUST BEAR THE UL94V-0 UL REGISTERED MATERIAL ID NUMBER" at 11361,2023.5 h60
  text "ADDITIONAL REQUIREMENTS:" at 11333.46,1854.08 h60
  text "MICROSECTION:" at 11408.23,1746.95 h60
  text "YES" at 12313.96,1746.95 h60
  text "REQUIRED" at 13175.46,1602.62 h60
  text "BARE BOARD ELEC. TEST:" at 11408.23,1599.76 h60
  text "NONE" at 12713.96,1599.76 h60
  text "X" at 13057.46,1599.76 h60
  text "PER ORDER" at 13767.46,1599.76 h60
  text "XX MIL VIAS REQUIRE NON-CONDUCTIVE FILL AND PLANARIZE" at 11576.38,1394.82 h59
  text "XX MIL VIAS REQUIRE CONDUCTIVE FILL AND PLANARIZE" at 11584.38,1290.84 h60
  text "OUTER XX MIL VIAS REQUIRE 50 OHM SINGLE-ENDED IMPEDANCE" at 11583.39,1127.46 h58
  text "LAYER 2 & 3 (INNER LAYERS) XX MIL WIDE, XX MIL SPACE / TRACES REQUIRE 100 OHM DIFFERENTIAL IMPEDANCE" at 11575.39,891.74 h60
  text ".Layer_Name" at 577,-858.49 h60
M11 Gerber Information:
  lines w10: -292,-930.17 6308,-930.17 ; -292,-726.83 6310,-726.83 ; -292,-523.5 -292,-1133.5 3713,-1133.5 6310,-1133.5 6310,-523.5 -291.5,-523.5 -291.5,-1133.5 1284,-1133.5 ; 2173,-1133.5 2173,-523.5 ; 3440,-726.83 3440,-523.5 ; 4280,-726.83 4280,-523.5 ; 4902,-1140 4902,-937.17
  text "ALL ARTWORK VIEWED FROM TOP SIDE" at -228.5,-655.67 h60
  text "BOARD #:" at 2248,-655.67 h60
  text ".PRJ_Number" at 2793.5,-655.67 h60
  text "REV:" at 3638,-655.67 h60
  text ".PCB_Rev" at 3929.5,-655.67 h60
  text "SVN REV:" at 4476,-655.67 h60
  text ".VersionControl_RevNumber" at 4982,-655.67 h60
  text "LAYER NAME =" at -228.5,-858.49 h60
  text "TID #:" at 2248,-859 h60
  text ".TID" at 2793.5,-859 h60
  text "PLOT NAME =" at -228.5,-1064.34 h60
  text ".plot_File_Name" at 577,-1064.34 h60
  text "GENERATED    :" at 2250,-1064.34 h60
  text ".Print_Date" at 3119.5,-1064.34 h60
  text ".Print_Time" at 3848.5,-1064.34 h60
  text "TEXAS INSTRUMENTS" at 5113,-1064.34 h60
M12 Stackup:
  drawing of 191 lines, arcs and shapes, not listed
  text "Layer" at 9790.34,7830 h60
  text "Name" at 10200.26,7830 h60
  text "Material" at 11130,7830 h60
  text "Thickness" at 11989.77,7830 h60
  text "Constant" at 12639.6,7830 h60
  text "Board Layer Stack" at 13209.46,7830 h60
  text "1" at 9790.34,7710 h60
  text "Top Overlay" at 10200.26,7710 h60
  text "2" at 9790.34,7590 h60
  text "Top Solder" at 10200.26,7590 h60
  text "Solder Resist" at 11130,7590 h60
  text "0.40mil" at 11989.77,7590 h60
  text "3.5" at 12639.6,7590 h60
  text "3" at 9790.34,7470 h60
  text "Top Layer" at 10200.26,7470 h60
  text "Copper" at 11130,7470 h60
  text "1.40mil" at 11989.77,7470 h60
  text "4" at 9790.34,7350 h60
  text "Dielectric1" at 10200.26,7350 h60
  text "FR-4" at 11130,7350 h60
  text "59.20mil" at 11989.77,7350 h60
  text "4.8" at 12639.6,7350 h60
  text "5" at 9790.34,7230 h60
  text "Bottom Layer" at 10200.26,7230 h60
  text "Copper" at 11130,7230 h60
  text "1.40mil" at 11989.77,7230 h60
  text "6" at 9790.34,7110 h60
  text "Bottom Solder" at 10200.26,7110 h60
  text "Solder Resist" at 11130,7110 h60
  text "0.40mil" at 11989.77,7110 h60
  text "3.5" at 12639.6,7110 h60
  text "7" at 9790.34,6990 h60
  text "Bottom Overlay" at 10200.26,6990 h60
  text ".Layer_Name" at 577,-858.49 h60
M13 Component Bodies Top:
  text ".Layer_Name" at 577,-858.49 h60
M14 Component Bodies Bottom:
  text ".Layer_Name" at 577,-858.49 h60
M15 Courtyards Top:
  text ".Layer_Name" at 577,-858.49 h60
M16 Courtyards Bottom:
  text ".Layer_Name" at 577,-858.49 h60
Drill Drawing:
  circle w10: c5348.9,2705.05 r22.14
  lines w10: 5326.76,2826.81 5371.04,2826.81 5348.9,2782.53 5326.76,2826.81 ; 5326.76,2882.15 5371.04,2882.15 5371.04,2926.43 5326.76,2926.43 5326.76,2882.15 ; 5326.76,2981.77 5371.04,2981.77 5371.04,3026.05 5326.76,3026.05 5326.76,2981.77 ; 5326.76,3103.54 5348.9,3081.4 5371.04,3103.54 5348.9,3125.67 5326.76,3103.54 ; 5326.76,3181.02 5348.9,3192.09 5371.04,3181.02 5359.97,3203.16 5371.04,3225.3 5348.9,3214.23 5326.76,3225.3 5337.83,3203.16 5326.76,3181.02 ; 5326.76,3291.71 5337.83,3291.71 5348.9,3280.64 5359.97,3291.71 5371.04,3291.71 5359.97,3302.78 5371.04,3313.85 5359.97,3313.85 5348.9,3324.92 5337.83,3313.85 5326.76,3313.85 5337.83,3302.78 5326.76,3291.71 ; 5335.62,2891.01 5362.18,2891.01 5362.18,2917.57 5335.62,2917.57 5335.62,2891.01
  lines w12: 5286,2653.02 8398.94,2653.02 ; 5286,3350.38 8398.94,3350.38 ; 5601.63,2553.4 5601.63,3450 ; 5918.82,2553.4 5918.82,3450 ; 6540.56,2553.4 6540.56,3450 ; 6784.88,2553.4 6784.88,3450 ; 7145.22,2553.4 7145.22,3450 ; 7854.73,2553.4 7854.73,3450 ; 5286,2553.4 8398.94,2553.4 8398.94,3450 5286,3450 5286,2553.4
  text "Symbol" at 5345.77,3380.26 h72
  text "Quantity" at 5631.52,3380.26 h72
  text "Finished Hole Size" at 5948.7,3380.26 h72
  text "Plated" at 6570.45,3380.26 h72
  text "Hole Type" at 6814.77,3380.26 h72
  text "Drill Layer Pair" at 7175.11,3380.26 h72
  text "Hole Tolerance" at 7884.62,3380.26 h72
  text "8" at 5631.52,3280.64 h60
  text "7.87mil (0.200mm)" at 5948.7,3280.64 h60
  text "PTH" at 6570.45,3280.64 h60
  text "Round" at 6814.77,3280.64 h60
  text "Top Layer - Bottom Layer" at 7175.11,3280.64 h60
  text "9" at 5631.52,3181.02 h60
  text "15.00mil (0.381mm)" at 5948.7,3181.02 h60
  text "PTH" at 6570.45,3181.02 h60
  text "Round" at 6814.77,3181.02 h60
  text "Top Layer - Bottom Layer" at 7175.11,3181.02 h60
  text "7" at 5631.52,3081.4 h60
  text "28.00mil (0.711mm)" at 5948.7,3081.4 h60
  text "PTH" at 6570.45,3081.4 h60
  text "Round" at 6814.77,3081.4 h60
  text "Top Layer - Bottom Layer" at 7175.11,3081.4 h60
  text "2" at 5631.52,2981.77 h60
  text "43.31mil (1.100mm)" at 5948.7,2981.77 h60
  text "PTH" at 6570.45,2981.77 h60
  text "Round" at 6814.77,2981.77 h60
  text "Top Layer - Bottom Layer" at 7175.11,2981.77 h60
  text "6" at 5631.52,2882.15 h60
  text "50.00mil (1.270mm)" at 5948.7,2882.15 h60
  text "PTH" at 6570.45,2882.15 h60
  text "Round" at 6814.77,2882.15 h60
  text "Top Layer - Bottom Layer" at 7175.11,2882.15 h60
  text "8" at 5631.52,2782.53 h60
  text "63.00mil (1.600mm)" at 5948.7,2782.53 h60
  text "PTH" at 6570.45,2782.53 h60
  text "Round" at 6814.77,2782.53 h60
  text "Top Layer - Bottom Layer" at 7175.11,2782.53 h60
  text "4" at 5631.52,2682.91 h60
  text "125.98mil (3.200mm)" at 5948.7,2682.91 h60
  text "PTH" at 6570.45,2682.91 h60
  text "Round" at 6814.77,2682.91 h60
  text "Top Layer - Bottom Layer" at 7175.11,2682.91 h60
  text "44 Total" at 5631.52,2583.29 h60
  text ".Layer_Name" at 577,-858.49 h60
M17 Embedded Cavity:
  text ".Layer_Name" at 577,-858.49 h60
M18 Embedded Assembly:
  text ".Layer_Name" at 577,-858.49 h60
M19 Embedded Keepout:
  text ".Layer_Name" at 577,-858.49 h60

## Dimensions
0,0 to 2285,0 on M2 Board Dimensions
0,0 to 0,2910 on M2 Board Dimensions
0,-400 to 1000,-400 on M2 Board Dimensions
